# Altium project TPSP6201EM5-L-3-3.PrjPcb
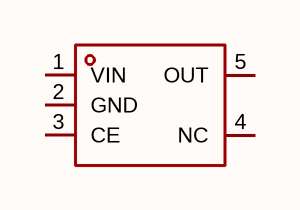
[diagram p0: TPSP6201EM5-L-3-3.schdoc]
1 sheet, 1 parts. Net scope: global (net labels, ports and power ports of the same name join across sheets).

## Sheet TPSP6201EM5-L-3-3.schdoc
size 127 x 101 mm

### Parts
U?  tpsp6201em5-l-3-3  [SOT-23-5_L2.9-W1.6-P0.95-LS2.8-BR]  (value not drawn)

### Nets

Not connected (* = marked no-connect by the designer): U? 1(VIN) 2(GND) 3(CE) 4(NC) 5(OUT)

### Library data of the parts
U? = tpsp6201em5-l-3-3: 输出极性:正极;工作电压:5.5V;输出电压:3.3V;输出电流:200mA;电源纹波抑制比(PSRR):75dB@(1kHz);输出类型:固定;; Manufacturer: TECH PUBLIC(台舟); AddInBom: yes; ModelId: 7ba65df16e7b4570af156e925f9c37fe; ModelTransform: 114.173,114.173,0,90,0,0,0,0,0; Output Configuration: 正极; Voltage - Supply: 5.5V; Output Voltage: 3.3V; Output Current: 200mA; Voltage Dropout: 180mV@(300mA); standby current: 6uA; Output Type: 固定; Number of Outputs: 1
